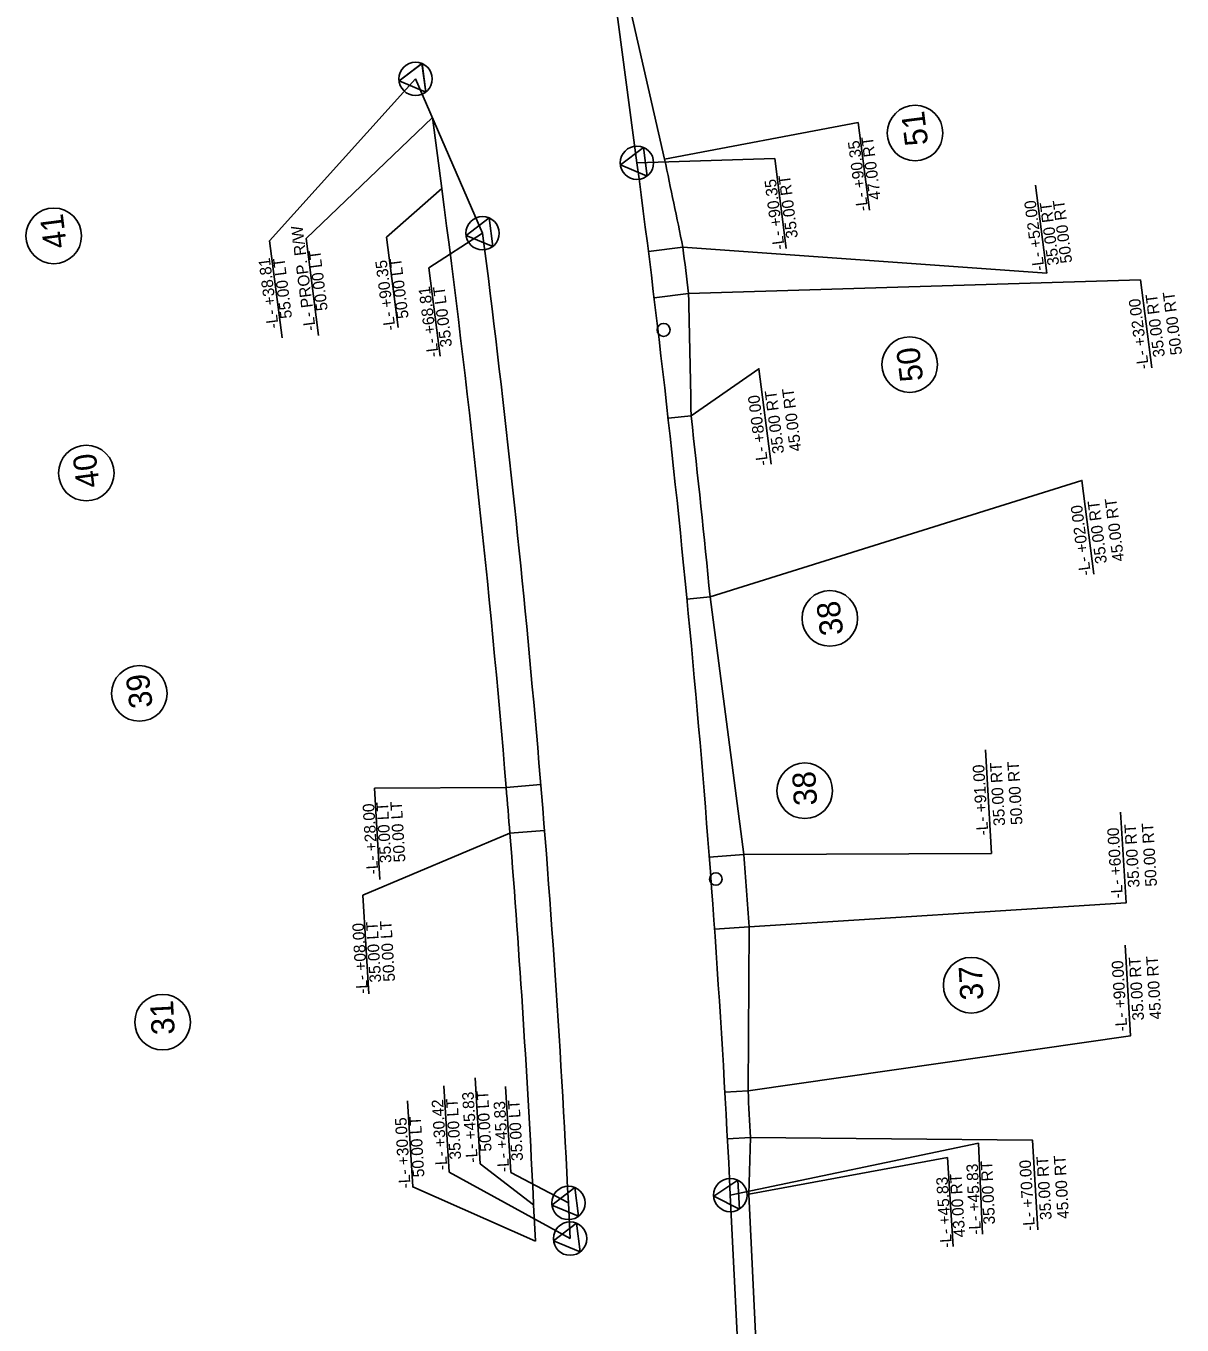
# Model space of a CAD drawing. Extents: x 2368169 to 2369183, y 801414 to 808542.
# Drawn here: x 2368524 to 2369023, y 804618 to 805179 of the extents above; entities that cross this region are included whole.
import ezdxf

# ---------------------------------------------------------------- set-up
doc = ezdxf.new("R2010")
doc.units = 0
for name, color, linetype in [('Prop Easement Construction', 7, 'Continuous'), ('Prop Easement Construction Station Offsets', 7, 'Continuous'), ('Prop Easement Permanent Drainage', 7, 'Continuous'), ('Prop Easement Permanent Drainage Station Offsets', 7, 'Continuous'), ('Prop Easement Permanent Drainage Utility', 7, 'Continuous'), ('Prop Easement Permanent Drainage Utility Station Offsets', 7, 'Continuous'), ('Prop Easement Permanent Utility', 7, 'Continuous'), ('Prop Easement Permanent Utility Station Offsets', 7, 'Continuous'), ('Prop Parcel Number CELL', 7, 'Continuous'), ('Prop Parcel Number Text', 7, 'Continuous'), ('Prop ROW Marker CELL', 7, 'Continuous'), ('Prop ROW RW Lines', 7, 'Continuous'), ('Prop ROW Station Offsets', 7, 'Continuous'), ('Scratch_Level_3', 7, 'Continuous')]:
    doc.layers.add(name, color=color, linetype=linetype)

msp = doc.modelspace()

# ---------------------------------------------------------------- linework, layer by layer
at = {"layer": 'Prop Easement Construction'}
for p, q in [((2368799.74, 805121.54), (2368783, 805194.63)), ((2368834, 804821.46), (2368819.37, 804932.59)), ((2368835.77, 804719.46), (2368836.28, 804790.25)), ((2368836.13, 804674.88), (2368836.89, 804699.32)), ((2368849.63, 804398.47), (2368836.13, 804674.88))]:
    msp.add_line(p, q, dxfattribs=at)
msp.add_arc((2363486.62, 803994.56), 5431.32, 11.56628, 11.97569, dxfattribs=at)
at = {"layer": 'Prop Easement Construction Station Offsets'}
for p, q in [((2368883.32, 805137.4), (2368799.74, 805121.54)), ((2368888.15, 805099.59), (2368883.32, 805137.4)), ((2368921.95, 804690.75), (2368836.13, 804674.88)), ((2368924.28, 804652.28), (2368921.95, 804690.75))]:
    msp.add_line(p, q, dxfattribs=at)
at = {"layer": 'Prop Easement Permanent Drainage'}
for p, q in [((2368807.65, 805083.54), (2368792.77, 805081.68)), ((2368810.12, 805063.51), (2368795.23, 805061.7)), ((2368811.22, 805010.82), (2368801.29, 805009.72)), ((2368819.37, 804932.59), (2368809.42, 804931.63)), ((2368835.77, 804719.46), (2368825.79, 804718.89)), ((2368836.89, 804699.32), (2368826.9, 804698.79))]:
    msp.add_line(p, q, dxfattribs=at)
for centre, radius, start, end in [((2363435.98, 804411.31), 5413.57, 6.91947, 7.13311), ((2363433, 804410.95), 5411.57, 5.53153, 6.36429), ((2363433, 804410.95), 5411.57, 3.0546, 3.26813)]:
    msp.add_arc(centre, radius, start, end, dxfattribs=at)
at = {"layer": 'Prop Easement Permanent Drainage Station Offsets'}
for p, q in [((2368964.7, 805072.4), (2368959.85, 805110.32)), ((2368964.7, 805072.4), (2368807.65, 805083.54)), ((2369005.24, 805069.48), (2368810.12, 805063.51)), ((2369010.09, 805031.53), (2369005.24, 805069.48))]:
    msp.add_line(p, q, dxfattribs=at)
for points in [[(2368845.72, 804989.88), (2368840.46, 805031.06), (2368811.22, 805010.82)], [(2368985.07, 804942.41), (2368979.9, 804982.91), (2368819.37, 804932.59)], [(2368998.55, 804782.36), (2369000.91, 804743.26), (2368835.77, 804719.46)], [(2368960.9, 804659.44), (2368958.56, 804698.23), (2368836.89, 804699.32)]]:
    msp.add_lwpolyline(points, dxfattribs=at)
at = {"layer": 'Prop Easement Permanent Drainage Utility'}
for p, q in [((2368731.38, 804850.42), (2368746.33, 804851.66)), ((2368732.98, 804830.67), (2368747.93, 804831.86)), ((2368834, 804821.46), (2368819.04, 804820.32)), ((2368836.28, 804790.25), (2368821.31, 804789.2))]:
    msp.add_line(p, q, dxfattribs=at)
for centre, radius, start, end in [((2363433, 804410.95), 5316.57, 4.52795, 4.74148), ((2361812.3, 804293.24), 7041.54, 4.047511, 4.302102)]:
    msp.add_arc(centre, radius, start, end, dxfattribs=at)
at = {"layer": 'Prop Easement Permanent Drainage Utility Station Offsets'}
for p, q in [((2368938.25, 804866.63), (2368940.94, 804821.9)), ((2368674.46, 804850.06), (2368731.38, 804850.42)), ((2368674.46, 804850.06), (2368676.83, 804810.64)), ((2368669.55, 804803.95), (2368732.98, 804830.67)), ((2368940.94, 804821.9), (2368834, 804821.46)), ((2368672.11, 804761.37), (2368669.55, 804803.95))]:
    msp.add_line(p, q, dxfattribs=at)
msp.add_lwpolyline([(2368996.64, 804839.72), (2368998.99, 804800.59), (2368836.28, 804790.25)], dxfattribs=at)
at = {"layer": 'Prop Easement Permanent Utility'}
for p, q in [((2368703.58, 805108.81), (2368699.51, 805139.5)), ((2368744.01, 804654.58), (2368743.24, 804670.35))]:
    msp.add_line(p, q, dxfattribs=at)
for centre, radius, start, end in [((2363433, 804410.95), 5316.57, 4.74148, 7.54241), ((2357029.66, 804790.91), 11783.61, 1.069377, 1.325611), ((2363433, 804410.95), 5316.57, 2.79654, 4.52795)]:
    msp.add_arc(centre, radius, start, end, dxfattribs=at)
at = {"layer": 'Prop Easement Permanent Utility Station Offsets'}
for p, q in [((2368645.06, 805087.35), (2368699.51, 805139.5)), ((2368679.77, 805087.92), (2368703.58, 805108.81)), ((2368684.75, 805048.96), (2368679.77, 805087.92)), ((2368650.41, 805045.42), (2368645.06, 805087.35)), ((2368717.95, 804725.07), (2368720.19, 804687.92)), ((2368720.19, 804687.92), (2368743.24, 804670.35))]:
    msp.add_line(p, q, dxfattribs=at)
msp.add_lwpolyline([(2368688.77, 804715.16), (2368691.01, 804678.01), (2368744.01, 804654.58)], dxfattribs=at)
at = {"layer": 'Prop Parcel Number CELL'}
for p, q in [((2368907.89, 805132.82), (2368907.89, 805132.82)), ((2368536.07, 805088.42), (2368536.07, 805088.42)), ((2368905.58, 805032.89), (2368905.58, 805032.89)), ((2368550.12, 804986.08), (2368550.12, 804986.08)), ((2368871.1, 804923.36), (2368871.1, 804923.36)), ((2368573.02, 804890.98), (2368573.02, 804890.98)), ((2368860.27, 804848.98), (2368860.27, 804848.98)), ((2368932.13, 804765.05), (2368932.13, 804765.05)), ((2368583.06, 804749.12), (2368583.06, 804749.12))]:
    msp.add_line(p, q, dxfattribs=at)
for centre in [(2368907.89, 805132.82), (2368536.07, 805088.42), (2368905.58, 805032.89), (2368550.12, 804986.08), (2368871.1, 804923.36), (2368573.02, 804890.98), (2368860.27, 804848.98), (2368932.13, 804765.05), (2368583.06, 804749.12)]:
    msp.add_circle(centre, 12, dxfattribs=at)
at = {"layer": 'Prop ROW Marker CELL'}
for p, q in [((2368692.26, 805156.2), (2368692.26, 805156.2)), ((2368692.26, 805156.2), (2368692.26, 805156.2)), ((2368787.84, 805119.96), (2368787.84, 805119.96)), ((2368787.84, 805119.96), (2368787.84, 805119.96)), ((2368721.21, 805089.56), (2368721.21, 805089.56)), ((2368721.21, 805089.56), (2368721.21, 805089.56)), ((2368828.14, 804674.49), (2368828.14, 804674.49)), ((2368828.14, 804674.49), (2368828.14, 804674.49)), ((2368758.23, 804671.08), (2368758.23, 804671.08)), ((2368758.23, 804671.08), (2368758.23, 804671.08)), ((2368758.98, 804655.69), (2368758.98, 804655.69)), ((2368758.98, 804655.69), (2368758.98, 804655.69))]:
    msp.add_line(p, q, dxfattribs=at)
for points in [[(2368696.62, 805150.45), (2368685.11, 805155.29), (2368695.04, 805162.85)], [(2368696.63, 805150.46), (2368685.12, 805155.28), (2368695.03, 805162.86)], [(2368792.21, 805114.23), (2368780.7, 805119.04), (2368790.61, 805126.62)], [(2368792.2, 805114.22), (2368780.7, 805119.05), (2368790.62, 805126.62)], [(2368725.58, 805083.82), (2368714.07, 805088.64), (2368723.98, 805096.22)], [(2368725.57, 805083.81), (2368714.07, 805088.65), (2368723.99, 805096.21)], [(2368832.11, 804668.47), (2368820.95, 804674.06), (2368831.36, 804680.95)], [(2368832.11, 804668.47), (2368820.95, 804674.06), (2368831.36, 804680.95)], [(2368762.59, 804665.34), (2368751.08, 804670.16), (2368761, 804677.74)], [(2368762.59, 804665.33), (2368751.08, 804670.17), (2368761, 804677.73)], [(2368763.34, 804649.94), (2368751.83, 804654.78), (2368761.76, 804662.34)], [(2368763.35, 804649.95), (2368751.84, 804654.77), (2368761.75, 804662.35)]]:
    msp.add_lwpolyline(points, close=True, dxfattribs=at)
for centre in [(2368692.26, 805156.2), (2368787.84, 805119.96), (2368721.21, 805089.56), (2368758.23, 804671.08), (2368828.14, 804674.49), (2368758.98, 804655.69)]:
    msp.add_circle(centre, 7.2, dxfattribs=at)
at = {"layer": 'Prop ROW RW Lines'}
for p, q in [((2368787.84, 805119.96), (2368682.03, 805919.1)), ((2368721.21, 805089.56), (2368692.26, 805156.2)), ((2368848.47, 804258.34), (2368828.14, 804674.49)), ((2368758.98, 804655.69), (2368758.23, 804671.08))]:
    msp.add_line(p, q, dxfattribs=at)
for radius, end in [(5401.57, 7.54241), (5331.57, 7.31247)]:
    msp.add_arc((2363433, 804410.95), radius, 2.79654, end, dxfattribs=at)
at = {"layer": 'Prop ROW Station Offsets'}
for p, q in [((2368847.29, 805121.8), (2368787.84, 805119.96)), ((2368852.25, 805082.98), (2368847.29, 805121.8)), ((2368698.04, 805074.57), (2368721.21, 805089.56)), ((2368702.89, 805036.58), (2368698.04, 805074.57)), ((2368704.53, 804721.58), (2368706.77, 804684.43)), ((2368731.12, 804721.39), (2368733.35, 804684.24)), ((2368935.21, 804696.89), (2368828.14, 804674.49)), ((2368936.98, 804657.68), (2368935.21, 804696.89)), ((2368706.77, 804684.43), (2368758.98, 804655.69)), ((2368733.35, 804684.24), (2368758.23, 804671.08))]:
    msp.add_line(p, q, dxfattribs=at)
msp.add_lwpolyline([(2368634.61, 805044.37), (2368629.25, 805086.3), (2368692.26, 805156.2)], dxfattribs=at)
at = {"layer": 'Scratch_Level_3'}
for centre, radius in [((2368799.35, 805047.84), 2.82), ((2368821.9, 804810.88), 2.7)]:
    msp.add_circle(centre, radius, dxfattribs=at)

# ---------------------------------------------------------------- texts
at = {"layer": 'Prop Easement Construction Station Offsets'}
for s, rotation, p in [('-L- +90.35', 97.2784, (2368887.67, 805099.41)), ('47.00 RT', 97.2784, (2368893.1, 805104.28)), ('-L- +45.83', 93.4716, (2368923.8, 804651.89)), ('43.00 RT', 93.4716, (2368929.54, 804656.38))]:
    msp.add_text(s, height=5, rotation=rotation, dxfattribs=at).set_placement(p)
at = {"layer": 'Prop Easement Permanent Drainage Station Offsets'}
for s, rotation, p in [('-L- +52.00', 97.2784, (2368963.8, 805073.63)), ('35.00 RT', 97.2784, (2368970.12, 805076)), ('50.00 RT', 97.2784, (2368975.73, 805076.93)), ('-L- +32.00', 97.2784, (2369008.87, 805031.22)), ('35.00 RT', 97.2784, (2369015.77, 805036.38)), ('50.00 RT', 97.2784, (2369023.21, 805037.33)), ('35.00 RT', 97.2784, (2368851.4, 804994.74)), ('45.00 RT', 97.2784, (2368858.84, 804995.69)), ('-L- +80.00', 97.2784, (2368844.5, 804989.58)), ('-L- +02.00', 97.2784, (2368983.85, 804942.11)), ('35.00 RT', 97.2784, (2368990.75, 804947.26)), ('45.00 RT', 97.2784, (2368998.19, 804948.21)), ('-L- +90.00', 93.443, (2368999.53, 804745.26)), ('35.00 RT', 93.443, (2369006.76, 804749.95)), ('45.00 RT', 93.443, (2369014.25, 804750.4)), ('-L- +70.00', 93.443, (2368959.66, 804659.21)), ('35.00 RT', 93.443, (2368966.89, 804663.9)), ('45.00 RT', 93.443, (2368974.38, 804664.35))]:
    msp.add_text(s, height=5, rotation=rotation, dxfattribs=at).set_placement(p)
at = {"layer": 'Prop Easement Permanent Drainage Utility Station Offsets'}
for s, p in [('-L- +91.00', (2368939.54, 804829.82)), ('35.00 RT', (2368946.81, 804833.91)), ('50.00 RT', (2368954.3, 804834.36)), ('-L- +28.00', (2368676.19, 804813.01)), ('35.00 LT', (2368681.9, 804817.9)), ('50.00 LT', (2368687.89, 804818.26)), ('-L- +60.00', (2368997.62, 804802.62)), ('35.00 RT', (2369004.85, 804807.31)), ('50.00 RT', (2369012.33, 804807.76)), ('-L- +08.00', (2368671.71, 804761.46)), ('35.00 LT', (2368677.43, 804766.35)), ('50.00 LT', (2368683.42, 804766.71))]:
    msp.add_text(s, height=5, rotation=93.443, dxfattribs=at).set_placement(p)
at = {"layer": 'Prop Easement Permanent Utility Station Offsets'}
for s, rotation, p in [('-L- PROP. R/W', 97.2784, (2368649.19, 805047.72)), ('50.00 LT', 97.2784, (2368654.38, 805056.39)), ('-L- +90.35', 97.2784, (2368683.65, 805047.85)), ('50.00 LT', 97.2784, (2368689.29, 805053.04)), ('-L- +45.83', 93.443, (2368719.12, 804688.61)), ('50.00 LT', 93.443, (2368725.09, 804693.41)), ('-L- +30.05', 93.443, (2368690.13, 804677.53)), ('50.00 LT', 93.443, (2368696.1, 804682.33))]:
    msp.add_text(s, height=5, rotation=rotation, dxfattribs=at).set_placement(p)
at = {"layer": 'Prop Parcel Number Text'}
for s, rotation, p in [('51', 97.2784, (2368913.61, 805127.94)), ('41', 97.2784, (2368541.8, 805083.59)), ('50', 97.2784, (2368911.48, 805026.15)), ('40', 97.2784, (2368555.97, 804980.29)), ('38', 97.2784, (2368877.01, 804916.6)), ('39', 97.2784, (2368578.87, 804885.19)), ('38', 93.443, (2368865.65, 804842.81)), ('37', 92.9979, (2368937.45, 804758.83)), ('31', 92.9979, (2368588.33, 804743.88))]:
    msp.add_text(s, height=10, rotation=rotation, dxfattribs=at).set_placement(p)
at = {"layer": 'Prop ROW Station Offsets'}
for s, rotation, p in [('-L- +90.35', 97.2784, (2368851.65, 805082.78)), ('35.00 RT', 97.2784, (2368857.32, 805087.68)), ('-L- +38.81', 97.2784, (2368633.21, 805048.74)), ('55.00 LT', 97.2784, (2368638.96, 805053.06)), ('-L- +68.81', 97.2784, (2368702.28, 805036.42)), ('35.00 LT', 97.2784, (2368708.03, 805040.74)), ('-L- +30.42', 93.443, (2368705.98, 804685.34)), ('35.00 LT', 93.443, (2368711.96, 804689.97)), ('-L- +45.83', 93.443, (2368732.71, 804684.56)), ('35.00 LT', 93.443, (2368738.68, 804689.35)), ('-L- +45.83', 92.5764, (2368936.36, 804657.5)), ('35.00 RT', 92.5764, (2368942.42, 804661.91))]:
    msp.add_text(s, height=5, rotation=rotation, dxfattribs=at).set_placement(p)

doc.saveas('drawing.dxf')
